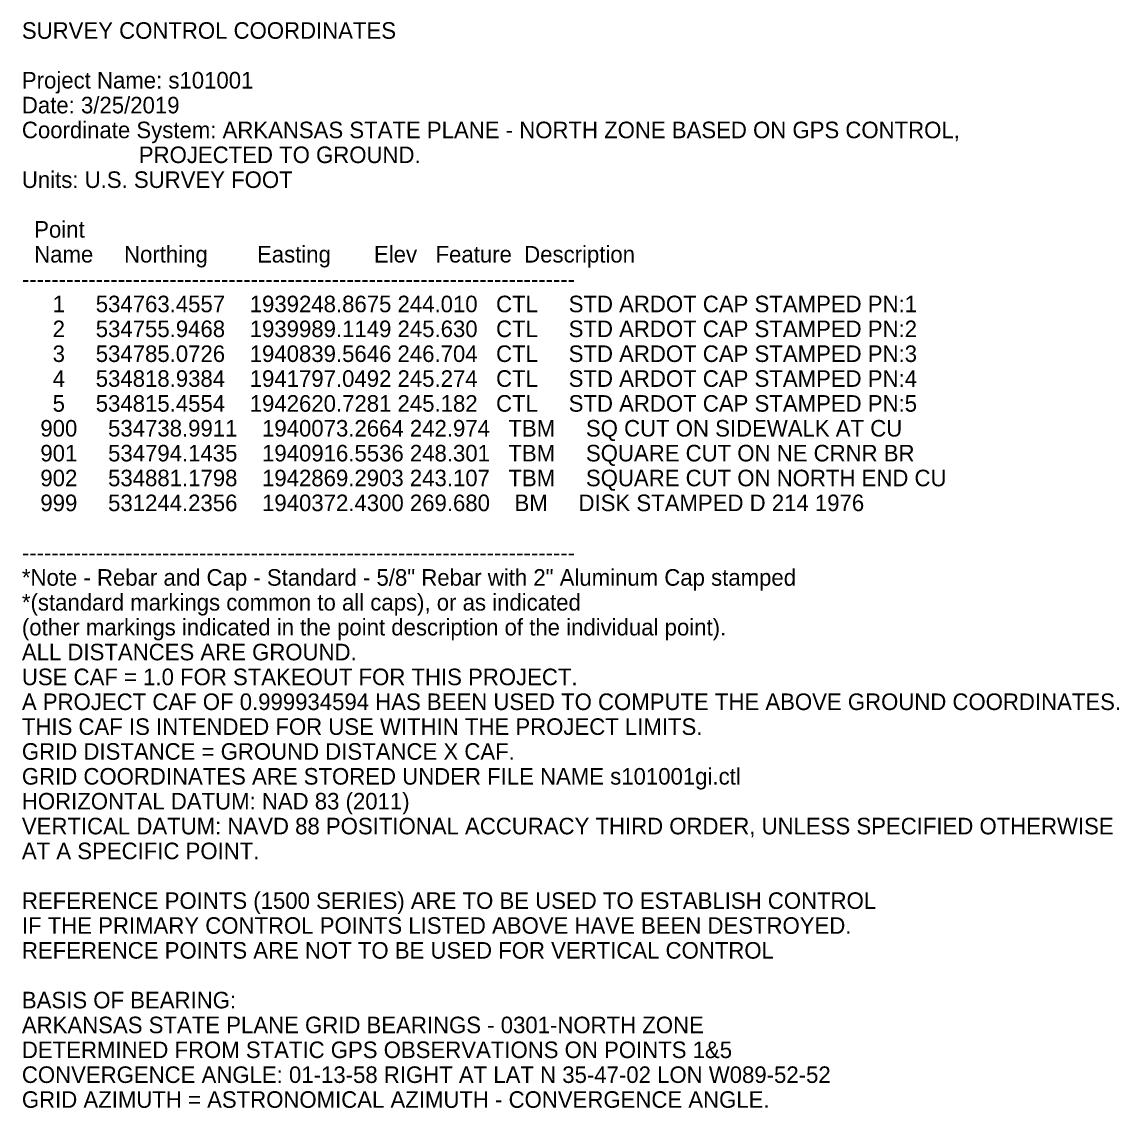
# Model space of a CAD drawing. Extents: x 1939239 to 1942996, y 531224 to 536374.
# Drawn here: x 1940859.7 to 1941190.8, y 536046.6 to 536374.2 of the extents above; entities that cross this region are included whole.
import ezdxf

# ---------------------------------------------------------------- set-up
doc = ezdxf.new("R2010")
doc.units = 0
doc.layers.add('Default', color=7, linetype='Continuous')

msp = doc.modelspace()

# ---------------------------------------------------------------- texts
at = {"layer": 'Default'}
for s, p in [('SURVEY CONTROL COORDINATES ', (1940859.67, 536369.12)), ('Project Name: s101001 ', (1940859.67, 536354.12)), ('Date: 3/25/2019 ', (1940859.67, 536346.62)), ('Coordinate System: ARKANSAS STATE PLANE - NORTH ZONE BASED ON GPS CONTROL, ', (1940859.67, 536339.12)), ('                   PROJECTED TO GROUND. ', (1940859.67, 536331.62)), ('Units: U.S. SURVEY FOOT ', (1940859.67, 536324.12)), ('  Point ', (1940859.67, 536309.12)), ('  Name     Northing        Easting       Elev   Feature  Description ', (1940859.67, 536301.62)), ('--------------------------------------------------------------------------- ', (1940859.67, 536294.12)), ('     1     534763.4557    1939248.8675 244.010   CTL    \xa0STD ARDOT CAP STAMPED PN:1 ', (1940859.67, 536286.62)), ('     2     534755.9468    1939989.1149 245.630   CTL    \xa0STD ARDOT CAP STAMPED PN:2 ', (1940859.67, 536279.12)), ('     3     534785.0726    1940839.5646 246.704   CTL    \xa0STD ARDOT CAP STAMPED PN:3 ', (1940859.67, 536271.62)), ('     4     534818.9384    1941797.0492 245.274   CTL    \xa0STD ARDOT CAP STAMPED PN:4 ', (1940859.67, 536264.12)), ('     5     534815.4554    1942620.7281 245.182   CTL    \xa0STD ARDOT CAP STAMPED PN:5 ', (1940859.67, 536256.62)), ('   900     534738.9911    1940073.2664 242.974   TBM    \xa0SQ CUT ON SIDEWALK AT CU ', (1940859.67, 536249.12)), ('   901     534794.1435    1940916.5536 248.301   TBM    \xa0SQUARE CUT ON NE CRNR BR ', (1940859.67, 536241.62)), ('   902     534881.1798    1942869.2903 243.107   TBM    \xa0SQUARE CUT ON NORTH END CU ', (1940859.67, 536234.12)), ('   999     531244.2356    1940372.4300 269.680    BM    \xa0DISK STAMPED D 214 1976 ', (1940859.67, 536226.62)), ('--------------------------------------------------------------------------- ', (1940859.67, 536211.62)), ('*Note - Rebar and Cap - Standard - 5/8" Rebar with 2" Aluminum Cap stamped ', (1940859.67, 536204.12)), ('*(standard markings common to all caps), or as indicated ', (1940859.67, 536196.62)), ('(other markings indicated in the point description of the individual point).  ', (1940859.67, 536189.12)), ('ALL DISTANCES ARE GROUND. ', (1940859.67, 536181.62)), ('USE CAF = 1.0 FOR STAKEOUT FOR THIS PROJECT. ', (1940859.67, 536174.12)), ('A PROJECT CAF OF 0.999934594 HAS BEEN USED TO COMPUTE THE ABOVE GROUND COORDINATES. ', (1940859.67, 536166.62)), ('THIS CAF IS INTENDED FOR USE WITHIN THE PROJECT LIMITS. ', (1940859.67, 536159.12)), ('GRID DISTANCE = GROUND DISTANCE X CAF. ', (1940859.67, 536151.62)), ('GRID COORDINATES ARE STORED UNDER FILE NAME s101001gi.ctl', (1940859.67, 536144.12)), ('HORIZONTAL DATUM: NAD 83 (2011) ', (1940859.67, 536136.62)), ('VERTICAL DATUM: NAVD 88 POSITIONAL ACCURACY THIRD ORDER, UNLESS SPECIFIED OTHERWISE  ', (1940859.67, 536129.12)), ('AT A SPECIFIC POINT. ', (1940859.67, 536121.62)), ('REFERENCE POINTS (1500 SERIES) ARE TO BE USED TO ESTABLISH CONTROL ', (1940859.67, 536106.62)), ('IF THE PRIMARY CONTROL POINTS LISTED ABOVE HAVE BEEN DESTROYED. ', (1940859.67, 536099.12)), ('REFERENCE POINTS ARE NOT TO BE USED FOR VERTICAL CONTROL ', (1940859.67, 536091.62)), ('BASIS OF BEARING: ', (1940859.67, 536076.62)), ('ARKANSAS STATE PLANE GRID BEARINGS - 0301-NORTH ZONE', (1940859.67, 536069.12)), ('DETERMINED FROM STATIC GPS OBSERVATIONS ON POINTS 1&5 ', (1940859.67, 536061.62)), ('CONVERGENCE ANGLE: 01-13-58 RIGHT AT LAT N 35-47-02 LON W089-52-52 ', (1940859.67, 536054.12)), ('GRID AZIMUTH = ASTRONOMICAL AZIMUTH - CONVERGENCE ANGLE. ', (1940859.67, 536046.62))]:
    msp.add_text(s, height=5, dxfattribs=at).set_placement(p)

doc.saveas('drawing.dxf')
